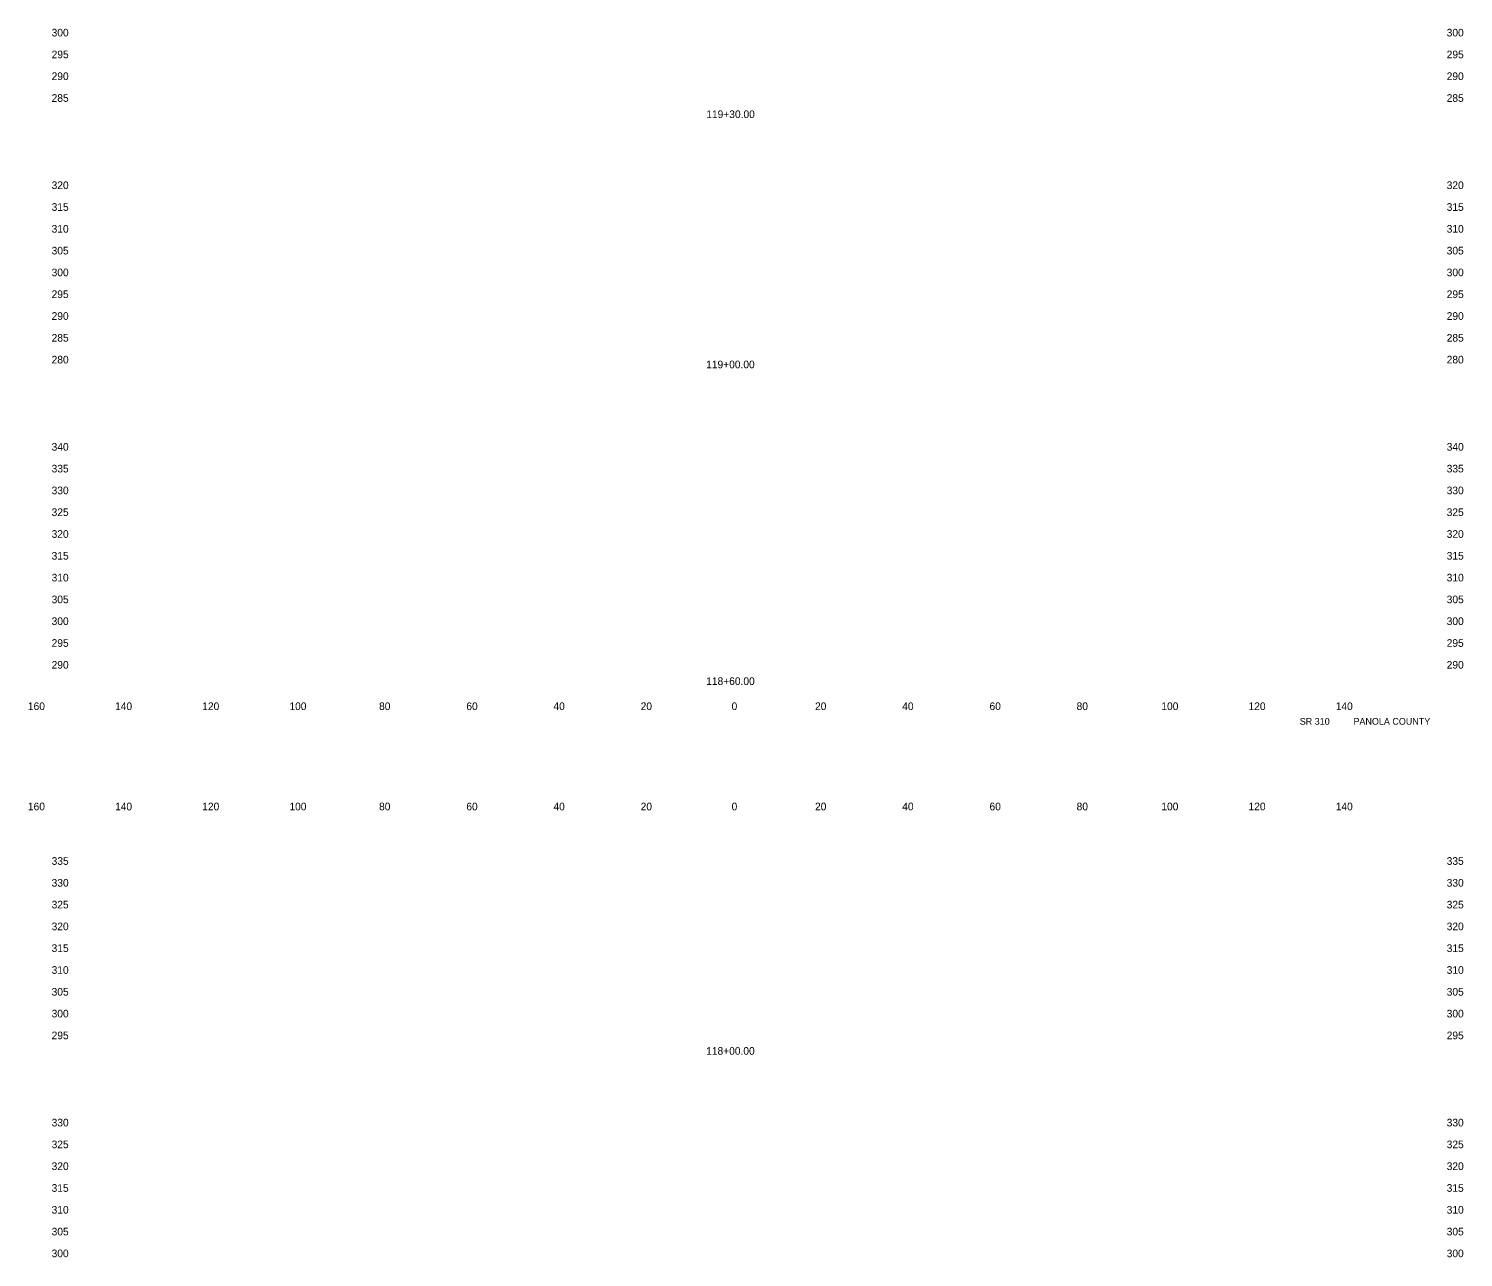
# Model space of a CAD drawing. Extents: x 21481 to 21810, y 6485 to 11067.
# Drawn here: x 21480.9 to 21809.9, y 8202.7 to 8484.5 of the extents above; entities that cross this region are included whole.
import ezdxf

# ---------------------------------------------------------------- set-up
doc = ezdxf.new("R2010")
doc.units = 0
for name, color, linetype in [('62', 7, 'Continuous'), ('XS_CELL', 7, 'Continuous'), ('XS_P_TX_DCH', 7, 'Continuous'), ('XS_P_TX_FS_BS', 7, 'Continuous')]:
    doc.layers.add(name, color=color, linetype=linetype)

msp = doc.modelspace()

# ---------------------------------------------------------------- texts
at = {"layer": '62'}
for s, p in [('  160  ', (21479.4, 8328.21)), ('  140  ', (21499.39, 8328.21)), ('  120  ', (21519.39, 8328.21)), ('  100  ', (21539.39, 8328.21)), ('  80  ', (21559.95, 8328.21)), ('  60  ', (21579.97, 8328.21)), ('  40  ', (21599.95, 8328.21)), ('  20  ', (21619.95, 8328.21)), ('  0  ', (21640.81, 8328.21)), ('  0  ', (21640.81, 8328.21)), ('  20  ', (21659.95, 8328.21)), ('  40  ', (21679.95, 8328.21)), ('  60  ', (21699.97, 8328.21)), ('  80  ', (21719.95, 8328.21)), ('  100  ', (21739.39, 8328.21)), ('  120  ', (21759.39, 8328.21)), ('  140  ', (21779.39, 8328.21)), ('  160  ', (21479.4, 8305.21)), ('  140  ', (21499.39, 8305.21)), ('  120  ', (21519.39, 8305.21)), ('  100  ', (21539.39, 8305.21)), ('  80  ', (21559.95, 8305.21)), ('  60  ', (21579.97, 8305.21)), ('  40  ', (21599.95, 8305.21)), ('  20  ', (21619.95, 8305.21)), ('  0  ', (21640.81, 8305.21)), ('  0  ', (21640.81, 8305.21)), ('  20  ', (21659.95, 8305.21)), ('  40  ', (21679.95, 8305.21)), ('  60  ', (21699.97, 8305.21)), ('  80  ', (21719.95, 8305.21)), ('  100  ', (21739.39, 8305.21)), ('  120  ', (21759.39, 8305.21)), ('  140  ', (21779.39, 8305.21))]:
    msp.add_text(s, height=1.75, dxfattribs=at).set_placement(p)
at = {"layer": 'XS_CELL'}
for s, p in [('  300  ', (21484.84, 8482.71)), ('  300  ', (21804.84, 8482.71)), ('  295  ', (21484.84, 8477.71)), ('  295  ', (21804.84, 8477.71)), ('  290  ', (21484.84, 8472.71)), ('  290  ', (21804.84, 8472.71)), ('  285  ', (21484.84, 8467.71)), ('  285  ', (21804.84, 8467.71)), ('  320  ', (21484.84, 8447.71)), ('  320  ', (21804.84, 8447.71)), ('  315  ', (21484.84, 8442.71)), ('  315  ', (21804.84, 8442.71)), ('  310  ', (21484.84, 8437.71)), ('  310  ', (21804.84, 8437.71)), ('  305  ', (21484.84, 8432.71)), ('  305  ', (21804.84, 8432.71)), ('  300  ', (21484.84, 8427.71)), ('  300  ', (21804.84, 8427.71)), ('  295  ', (21484.84, 8422.71)), ('  295  ', (21804.84, 8422.71)), ('  290  ', (21484.84, 8417.71)), ('  290  ', (21804.84, 8417.71)), ('  285  ', (21484.84, 8412.71)), ('  285  ', (21804.84, 8412.71)), ('  280  ', (21484.84, 8407.71)), ('  280  ', (21804.84, 8407.71)), ('  340  ', (21484.84, 8387.71)), ('  340  ', (21804.84, 8387.71)), ('  335  ', (21484.84, 8382.71)), ('  335  ', (21804.84, 8382.71)), ('  330  ', (21484.84, 8377.71)), ('  330  ', (21804.84, 8377.71)), ('  325  ', (21484.84, 8372.71)), ('  325  ', (21804.84, 8372.71)), ('  320  ', (21484.84, 8367.71)), ('  320  ', (21804.84, 8367.71)), ('  315  ', (21484.84, 8362.71)), ('  315  ', (21804.84, 8362.71)), ('  310  ', (21484.84, 8357.71)), ('  310  ', (21804.84, 8357.71)), ('  305  ', (21484.84, 8352.71)), ('  305  ', (21804.84, 8352.71)), ('  300  ', (21484.84, 8347.71)), ('  300  ', (21804.84, 8347.71)), ('  295  ', (21484.84, 8342.71)), ('  295  ', (21804.84, 8342.71)), ('  290  ', (21484.84, 8337.71)), ('  290  ', (21804.84, 8337.71)), ('  335  ', (21484.84, 8292.71)), ('  335  ', (21804.84, 8292.71)), ('  330  ', (21484.84, 8287.71)), ('  330  ', (21804.84, 8287.71)), ('  325  ', (21484.84, 8282.71)), ('  325  ', (21804.84, 8282.71)), ('  320  ', (21484.84, 8277.71)), ('  320  ', (21804.84, 8277.71)), ('  315  ', (21484.84, 8272.71)), ('  315  ', (21804.84, 8272.71)), ('  310  ', (21484.84, 8267.71)), ('  310  ', (21804.84, 8267.71)), ('  305  ', (21484.84, 8262.71)), ('  305  ', (21804.84, 8262.71)), ('  300  ', (21484.84, 8257.71)), ('  300  ', (21804.84, 8257.71)), ('  295  ', (21484.84, 8252.71)), ('  295  ', (21804.84, 8252.71)), ('  330  ', (21484.84, 8232.71)), ('  330  ', (21804.84, 8232.71)), ('  325  ', (21484.84, 8227.71)), ('  325  ', (21804.84, 8227.71)), ('  320  ', (21484.84, 8222.71)), ('  320  ', (21804.84, 8222.71)), ('  315  ', (21484.84, 8217.71)), ('  315  ', (21804.84, 8217.71)), ('  310  ', (21484.84, 8212.71)), ('  310  ', (21804.84, 8212.71)), ('  305  ', (21484.84, 8207.71)), ('  305  ', (21804.84, 8207.71)), ('  300  ', (21484.84, 8202.71)), ('  300  ', (21804.84, 8202.71))]:
    msp.add_text(s, height=1.75, dxfattribs=at).set_placement(p)
at = {"layer": 'XS_P_TX_DCH'}
for s, p in [('  119+30.00  ', (21635.01, 8463.99)), ('  119+00.00  ', (21634.98, 8406.6)), ('  118+60.00  ', (21634.99, 8333.96)), ('  118+00.00  ', (21634.98, 8249.15))]:
    msp.add_text(s, height=1.75, dxfattribs=at).set_placement(p)
at = {"layer": 'XS_P_TX_FS_BS'}
for s, p in [('SR 310', (21772.43, 8324.84)), ('SR 310', (21772.43, 8324.84)), ('SR 310', (21772.43, 8324.84)), ('PANOLA COUNTY', (21784.75, 8324.84)), ('PANOLA COUNTY', (21784.75, 8324.84)), ('PANOLA COUNTY', (21784.75, 8324.84))]:
    msp.add_text(s, height=1.54, dxfattribs=at).set_placement(p)

doc.saveas('drawing.dxf')
